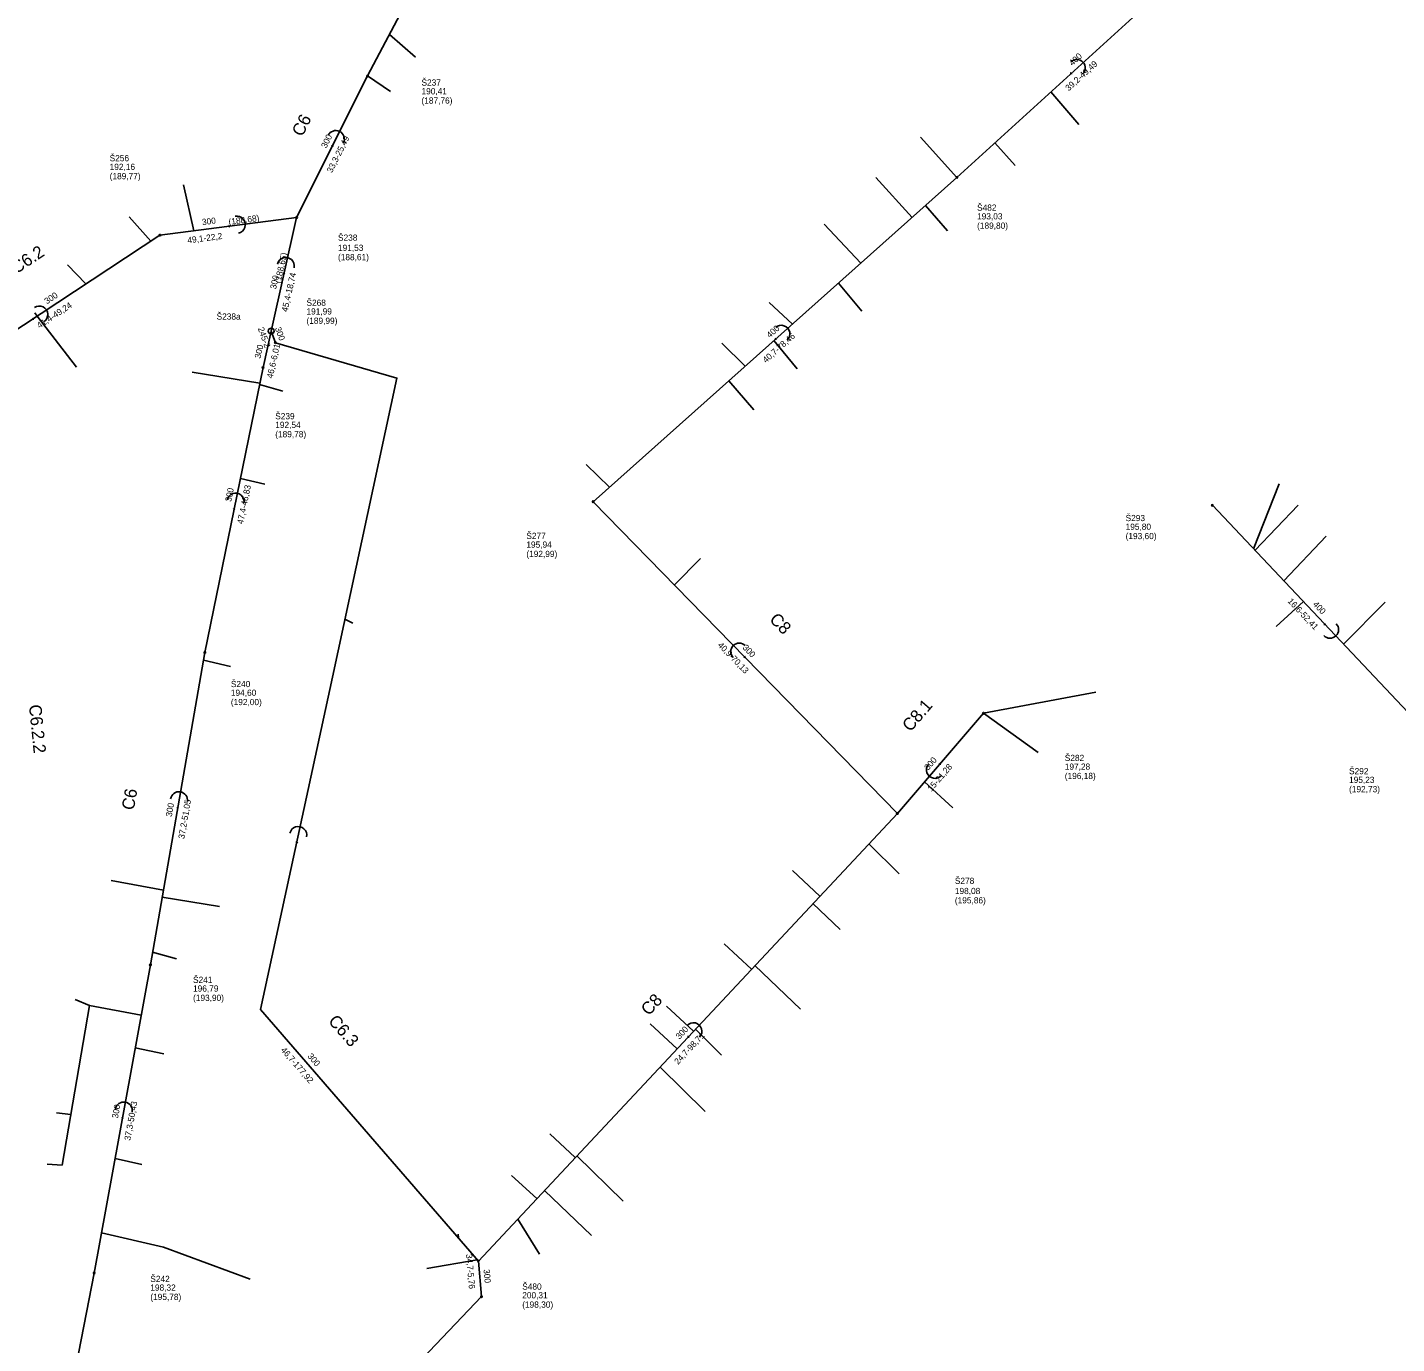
# Model space of a CAD drawing. Extents: x -548529 to -543591, y -1201432 to -1192608.
# Drawn here: x -547490.5 to -547270, y -1196012.4 to -1195800.5 of the extents above; entities that cross this region are included whole.
import ezdxf

# ---------------------------------------------------------------- set-up
doc = ezdxf.new("R2010")
doc.units = 0
for name, color, linetype in [('C3D_Bod-Značky', 7, 'Continuous'), ('C3D_Koridor', 7, 'Continuous'), ('C3D_Křižovatka', 7, 'Continuous'), ('C3D_Netisknutelná', 7, 'Continuous'), ('C3D_PP-zobrazeni v PR', 7, 'Continuous'), ('C3D_PR-Popisek', 7, 'Continuous'), ('C3D_SPR-Popisek', 7, 'Continuous'), ('C3D_Tlakove_potrubi_Popis', 7, 'Continuous'), ('C3D_ZPR-Formaty', 7, 'Continuous')]:
    doc.layers.add(name, color=color, linetype=linetype)

# ---------------------------------------------------------------- blocks, each defined once
blk = doc.blocks.new('100')
at = {"layer": 'Defpoints'}
blk.add_circle((0, 0), 0.127, dxfattribs=at)
blk = doc.blocks.new('101')
at = {"layer": 'Defpoints'}
blk.add_circle((0, 0), 0.463, dxfattribs=at)
blk = doc.blocks.new('91')
at = {"layer": 'Defpoints'}
blk.add_lwpolyline([(0.08, 0.14), (0.19, 0), (0.08, -0.14)], dxfattribs=at)
blk.add_arc((1.37, 0), 1.37, 270, 90, dxfattribs=at)
blk = doc.blocks.new('86')
at = {"layer": 'Defpoints'}
blk.add_lwpolyline([(0.08, 0.14), (0.19, 0), (0.08, -0.14)], dxfattribs=at)
blk.add_arc((1.37, 0), 1.37, 270, 90, dxfattribs=at)

msp = doc.modelspace()

# ---------------------------------------------------------------- linework, layer by layer
at = {"layer": 'C3D_Bod-Značky'}
for points in [[(-547435.695, -1195808.298), (-547423.237, -1195784.702)], [(-547340.806, -1195824.625), (-547304.215, -1195791.3)], [(-547447.117, -1195831.081), (-547435.695, -1195808.298)], [(-547399.369, -1195876.839), (-547340.806, -1195824.625)], [(-547469.132, -1195833.93), (-547447.117, -1195831.081)], [(-547451.21, -1195849.364), (-547447.117, -1195831.081)], [(-547510.241, -1195861.041), (-547469.132, -1195833.93)], [(-547417.852, -1195999.092), (-547452.911, -1195958.612), (-547441.362, -1195905.074), (-547430.982, -1195856.953), (-547450.533, -1195851.246)], [(-547452.523, -1195855.231), (-547451.21, -1195849.364)], [(-547450.533, -1195851.246), (-547451.21, -1195849.364)], [(-547461.897, -1195901.114), (-547452.523, -1195855.231)], [(-547350.394, -1195927.035), (-547399.369, -1195876.839)], [(-547299.67, -1195877.42), (-547263.673, -1195915.508)], [(-547470.656, -1195951.406), (-547461.897, -1195901.114)], [(-547336.515, -1195910.905), (-547350.394, -1195927.035)], [(-547417.852, -1195999.092), (-547350.394, -1195927.035)], [(-547479.714, -1196001.019), (-547470.656, -1195951.406)], [(-547487.211, -1196039.592), (-547479.714, -1196001.019)], [(-547417.348, -1196004.825), (-547417.852, -1195999.092)], [(-547462.506, -1196052.22), (-547417.348, -1196004.825)]]:
    msp.add_lwpolyline(points, dxfattribs=at)
at = {"layer": 'C3D_Koridor'}
for points in [[(-547432.165, -1195801.612), (-547428.005, -1195805.296)], [(-547435.695, -1195808.298), (-547432.018, -1195810.783)], [(-547325.693, -1195810.861), (-547321.16, -1195816.107)], [(-547340.813, -1195824.631), (-547346.655, -1195818.138)], [(-547334.684, -1195819.049), (-547331.451, -1195822.702)], [(-547348.031, -1195831.067), (-547353.878, -1195824.653)], [(-547463.652, -1195833.221), (-547465.359, -1195825.85)], [(-547345.866, -1195829.137), (-547342.334, -1195833.221)], [(-547470.601, -1195834.899), (-547474.063, -1195830.964)], [(-547356.271, -1195838.414), (-547362.191, -1195832.153)], [(-547481.047, -1195841.788), (-547484.006, -1195838.7)], [(-547359.884, -1195841.634), (-547356.134, -1195846.159)], [(-547488.881, -1195846.955), (-547489.284, -1195846.449)], [(-547367.296, -1195848.243), (-547371.057, -1195844.789)], [(-547488.881, -1195846.955), (-547482.563, -1195855.161)], [(-547374.896, -1195855.019), (-547378.646, -1195851.298)], [(-547370.281, -1195850.905), (-547366.514, -1195855.469)], [(-547453.038, -1195857.754), (-547463.918, -1195855.982)], [(-547377.522, -1195857.36), (-547373.487, -1195862.046)], [(-547453.086, -1195857.985), (-547449.327, -1195859.064)], [(-547396.765, -1195874.517), (-547400.495, -1195870.84)], [(-547456.175, -1195873.109), (-547452.256, -1195874.033)], [(-547293.064, -1195884.41), (-547288.904, -1195873.971)], [(-547292.809, -1195884.677), (-547285.836, -1195877.397)], [(-547288.159, -1195889.598), (-547281.341, -1195882.412)], [(-547386.295, -1195890.239), (-547382.115, -1195885.97)], [(-547285.007, -1195892.934), (-547289.404, -1195896.912)], [(-547278.558, -1195899.759), (-547271.859, -1195893.003)], [(-547439.355, -1195895.77), (-547438.084, -1195896.38)], [(-547462.116, -1195902.372), (-547457.748, -1195903.377)], [(-547336.515, -1195910.905), (-547318.43, -1195907.5)], [(-547336.515, -1195910.905), (-547327.697, -1195917.193)], [(-547345.998, -1195921.926), (-547341.485, -1195926.139)], [(-547354.97, -1195931.923), (-547350.094, -1195936.751)], [(-547362.85, -1195940.34), (-547367.264, -1195936.218)], [(-547468.559, -1195939.365), (-547476.97, -1195937.809)], [(-547468.758, -1195940.507), (-547459.555, -1195942.025)], [(-547363.984, -1195941.552), (-547359.613, -1195945.728)], [(-547373.867, -1195952.108), (-547378.268, -1195948.043)], [(-547470.304, -1195949.385), (-547466.475, -1195950.425)], [(-547373.327, -1195951.531), (-547365.976, -1195958.53)], [(-547480.458, -1195957.961), (-547482.762, -1195956.987)], [(-547472.132, -1195959.489), (-547480.458, -1195957.961), (-547484.855, -1195983.677)], [(-547383.23, -1195962.109), (-547387.577, -1195958.076)], [(-547385.867, -1195964.927), (-547390.172, -1195960.881)], [(-547382.895, -1195961.751), (-547378.686, -1195965.94)], [(-547473.091, -1195964.741), (-547468.478, -1195965.716)], [(-547388.608, -1195967.854), (-547381.353, -1195975.026)], [(-547483.455, -1195975.487), (-547485.773, -1195975.213)], [(-547402.256, -1195982.433), (-547406.376, -1195978.586)], [(-547484.855, -1195983.677), (-547487.301, -1195983.509)], [(-547476.346, -1195982.571), (-547472.046, -1195983.552)], [(-547401.983, -1195982.141), (-547394.524, -1195989.443)], [(-547408.448, -1195989.047), (-547412.542, -1195985.317)], [(-547407.212, -1195987.726), (-547399.659, -1195994.989)], [(-547411.524, -1195992.332), (-547407.998, -1195998.009)], [(-547478.534, -1195994.554), (-547468.581, -1195996.84), (-547454.589, -1196002.001)], [(-547421.068, -1195995.378), (-547421.119, -1195994.75)], [(-547418.03, -1195998.886), (-547426.156, -1196000.305)]]:
    msp.add_lwpolyline(points, dxfattribs=at)

# ---------------------------------------------------------------- block references
at = {"layer": 'C3D_PP-zobrazeni v PR'}
for name, p, xscale, yscale, rotation in [('100', (-547435.695, -1195808.298), 0.9999999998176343, 0.9999999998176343, -116.9999993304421), ('100', (-547340.806, -1195824.625), 1.00000000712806, 1.00000000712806, -136.99999943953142), ('100', (-547447.117, -1195831.081), 1.00000000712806, 1.00000000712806, -46.99999943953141), ('100', (-547469.132, -1195833.93), 1.0275072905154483, 1.027507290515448, -155.31089431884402), ('101', (-547451.21, -1195849.364), 1.0045862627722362, 1.0045862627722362, -13.174090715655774), ('100', (-547450.533, -1195851.246), 1.00000000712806, 1.00000000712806, 136.99999943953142), ('100', (-547452.523, -1195855.231), 1.0000000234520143, 1.0000000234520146, -101.99999938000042), ('100', (-547399.369, -1195876.839), 1.000000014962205, 1.0000000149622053, 89.0000000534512), ('100', (-547299.67, -1195877.42), 1.0000000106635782, 1.0000000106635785, 134.00000165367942), ('100', (-547461.897, -1195901.114), 0.9999999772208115, 0.9999999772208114, -100.00000028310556), ('100', (-547336.515, -1195910.905), 1.0000000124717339, 1.0000000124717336, 49.99999868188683), ('100', (-547350.394, -1195927.035), 1.00000001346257, 1.0000000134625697, -178.0000000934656), ('100', (-547470.656, -1195951.406), 0.9999999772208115, 0.9999999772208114, -100.00000028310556), ('100', (-547417.852, -1195999.092), 0.9999999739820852, 0.9999999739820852, 68.99999941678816), ('100', (-547479.714, -1196001.019), 0.9999999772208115, 0.9999999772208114, -100.00000028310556), ('100', (-547417.348, -1196004.825), 0.999999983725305, 0.999999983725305, -109.00000122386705)]:
    msp.add_blockref(name, p, dxfattribs=dict(at, xscale=xscale, yscale=yscale, rotation=rotation))
at = {"layer": 'C3D_SPR-Popisek'}
for name, p, xscale, yscale, rotation in [('91', (-547322.511, -1195807.963), 1.00000000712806, 1.00000000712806, 43.0000005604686), ('91', (-547441.406, -1195819.689), 1.0000000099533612, 1.0000000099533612, 63.999999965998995), ('91', (-547458.124, -1195832.506), 1.0092050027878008, 1.0092050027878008, 11.116918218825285), ('91', (-547449.163, -1195840.223), 1.0000000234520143, 1.0000000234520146, 78.0000006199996), ('91', (-547489.687, -1195847.486), 0.9999999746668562, 0.999999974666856, 34.00000045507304), ('91', (-547370.088, -1195850.732), 1.0000000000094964, 1.0000000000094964, 42.000001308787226), ('91', (-547457.21, -1195878.172), 0.999999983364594, 0.9999999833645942, 78.9999997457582), ('91', (-547281.671, -1195896.464), 1.0000000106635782, 1.0000000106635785, -45.99999834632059), ('86', (-547374.882, -1195901.937), 0.999999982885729, 0.9999999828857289, 135), ('91', (-547343.454, -1195918.97), 1.0000000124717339, 1.0000000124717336, -130.0000013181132), ('91', (-547466.276, -1195926.26), 1.0000000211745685, 1.0000000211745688, 81.00000039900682), ('91', (-547447.137, -1195931.843), 1.0000000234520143, 1.0000000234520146, 78.0000006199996), ('91', (-547384.161, -1195963.104), 1.00000000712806, 1.00000000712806, 46.99999943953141), ('91', (-547475.185, -1195976.212), 0.9999999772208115, 0.9999999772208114, 79.99999971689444)]:
    msp.add_blockref(name, p, dxfattribs=dict(at, xscale=xscale, yscale=yscale, rotation=rotation))

# ---------------------------------------------------------------- texts
at = {"layer": 'C3D_Křižovatka'}
for s, p in [('Š237', (-547427.015, -1195809.858)), ('Š256', (-547477.222, -1195822.03)), ('Š482', (-547337.556, -1195829.995)), ('Š238', (-547440.457, -1195834.831)), ('Š268', (-547445.533, -1195845.306)), ('Š238a', (-547460, -1195847.524)), ('Š239', (-547450.563, -1195863.571)), ('Š293', (-547313.64, -1195879.97)), ('Š277', (-547410.129, -1195882.849)), ('Š240', (-547457.707, -1195906.694)), ('Š282', (-547323.435, -1195918.595)), ('Š292', (-547277.663, -1195920.718)), ('Š278', (-547341.134, -1195938.385)), ('Š241', (-547463.796, -1195954.316)), ('Š242', (-547470.674, -1196002.469)), ('Š480', (-547410.792, -1196003.702))]:
    msp.add_text(s, height=1, dxfattribs=at).set_placement(p)
at = {"layer": 'C3D_Netisknutelná'}
for s, rotation, p in [('C6', 63.37, (-547446.204, -1195818.19)), ('C6.2', 33.4, (-547492.262, -1195840.232)), ('C8', 314.29, (-547371.114, -1195895.919)), ('C6.2.2', 275.71, (-547490.221, -1195909.599)), ('C8.1', 49.29, (-547348.287, -1195914.004)), ('C6', 80.12, (-547473.335, -1195926.588)), ('C8', 46.89, (-547390.427, -1195959.707)), ('C6.3', 310.9, (-547442.133, -1195960.52))]:
    msp.add_text(s, height=2, rotation=rotation, dxfattribs=at).set_placement(p)
at = {"layer": 'C3D_PR-Popisek'}
for s, rotation, p in [('400', 42.33, (-547322.209, -1195806.746)), ('300', 63.37, (-547442.352, -1195820.012)), ('300', 7.37, (-547462.291, -1195832.335)), ('300', 77.38, (-547450.436, -1195842.694)), ('300', 33.4, (-547487.33, -1195845.087)), ('300', 289.78, (-547450.63, -1195848.909)), ('400', 41.72, (-547370.925, -1195850.546)), ('300', 77.38, (-547452.935, -1195853.856)), ('300', 78.45, (-547457.667, -1195876.912)), ('400', 313.38, (-547283.568, -1195893.444)), ('300', 314.29, (-547375.392, -1195900.419)), ('300', 49.29, (-547345.416, -1195920.171)), ('300', 80.12, (-547467.225, -1195927.633)), ('300', 46.89, (-547385.48, -1195963.484)), ('300', 310.9, (-547445.44, -1195966.166)), ('300', 79.65, (-547475.889, -1195976.181)), ('300', 275.02, (-547417.028, -1196000.449))]:
    msp.add_text(s, height=1, rotation=rotation, dxfattribs=at).set_placement(p)
at = {"layer": 'C3D_Tlakove_potrubi_Popis'}
for s, p in [('190,41 ', (-547427.015, -1195811.258)), ('(187,76)', (-547427.015, -1195812.758)), ('192,16 ', (-547477.222, -1195823.43)), ('(189,77)', (-547477.222, -1195824.93)), ('193,03 ', (-547337.556, -1195831.395)), ('(189,80)', (-547337.556, -1195832.895)), ('191,53 ', (-547440.457, -1195836.461)), ('(188,61)', (-547440.457, -1195837.961)), ('191,99 ', (-547445.533, -1195846.706)), ('(189,99)', (-547445.533, -1195848.206)), ('192,54 ', (-547450.563, -1195864.971)), ('(189,78)', (-547450.563, -1195866.471)), ('(193,60)', (-547313.64, -1195882.87)), ('195,80 ', (-547313.64, -1195881.37)), ('195,94 ', (-547410.129, -1195884.249)), ('(192,99)', (-547410.129, -1195885.749)), ('(192,00)', (-547457.707, -1195909.594)), ('194,60 ', (-547457.707, -1195908.094)), ('197,28 ', (-547323.435, -1195919.995)), ('(196,18)', (-547323.435, -1195921.495)), ('195,23 ', (-547277.663, -1195922.118)), ('(192,73)', (-547277.663, -1195923.618)), ('198,08 ', (-547341.134, -1195940.015)), ('(195,86)', (-547341.134, -1195941.515)), ('196,79 ', (-547463.796, -1195955.716)), ('(193,90)', (-547463.796, -1195957.216)), ('198,32 ', (-547470.674, -1196003.869)), ('(195,78)', (-547470.674, -1196005.369)), ('200,31 ', (-547410.792, -1196005.102)), ('(198,30)', (-547410.792, -1196006.602))]:
    msp.add_text(s, height=1, dxfattribs=at).set_placement(p)
at = {"layer": 'C3D_ZPR-Formaty'}
for s, rotation, p in [('39,2-49,49', 42.33, (-547322.795, -1195810.792)), ('33,3-25,49', 63.37, (-547441.432, -1195823.986)), ('  (188,68)   ', 7.37, (-547458.746, -1195832.383)), ('49,1-22,2', 7.37, (-547464.639, -1195835.26)), ('  (188,65)   ', 77.38, (-547449.868, -1195842.455)), ('45,4-18,74', 77.38, (-547448.588, -1195846.333)), ('41,4-49,24', 33.4, (-547488.519, -1195848.99)), ('245-2', 289.78, (-547453.382, -1195848.946)), ('40,7-78,46', 41.72, (-547371.544, -1195854.577)), ('46,6-6,01', 77.38, (-547450.989, -1195857.056)), ('47,4-46,83', 78.45, (-547455.746, -1195880.518)), ('16,6-52,41', 313.38, (-547287.619, -1195892.937)), ('40,9-70,13', 314.29, (-547379.393, -1195900.032)), ('15-21,28', 49.29, (-547344.912, -1195923.58)), ('37,2-51,05', 80.12, (-547465.206, -1195931.186)), ('24,7-98,71', 46.89, (-547385.7, -1195967.53)), ('46,7-177,92', 310.9, (-547449.735, -1195965.181)), ('37,3-50,43', 79.65, (-547473.898, -1195979.751)), ('34,7-5,76', 275.02, (-547419.859, -1195997.992))]:
    msp.add_text(s, height=1, rotation=rotation, dxfattribs=at).set_placement(p)

doc.saveas('drawing.dxf')
